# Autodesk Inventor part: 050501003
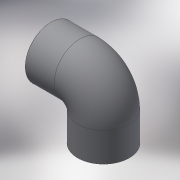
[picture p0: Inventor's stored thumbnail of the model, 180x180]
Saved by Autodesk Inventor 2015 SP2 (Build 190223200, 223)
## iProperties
Created: 2017-10
Part Number: 050501003
Material: Generic
Description: PLASSON THREADED 90° ELBOW PVC 3/8"
Document SubType Name: Modeling
Designer: KIM
Density: 1 g/cm^3
Appearance: Default
Author: KIM
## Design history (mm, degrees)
derived "050501.ipt"
feature "Solid1::050501.ipt"
tag "TaggingFeature1"
body "Solid1"
other parameters: "d7" = 0.1495, "d9" = 23, "d10" = 23.5, "d13" = 90 deg, "d19" = 90 deg, "d20" = 14.95, "d21" = 13, "d22" = 0, "d24" = 90 deg, "d26" = 13.455, "d27" = 90 deg, "d28" = 13, "G_" = 14.95, "E_" = 23, "H_" = 35, "lt_" = 13
